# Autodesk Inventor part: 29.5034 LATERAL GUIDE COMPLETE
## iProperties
Created: 2007-07
Part Number: 29.5034 LATERAL GUIDE COMPLETE
Document SubType Name: Modeling
Designer: Andy Moles
Material: Aluminum-6061
Author: Andy Moles
